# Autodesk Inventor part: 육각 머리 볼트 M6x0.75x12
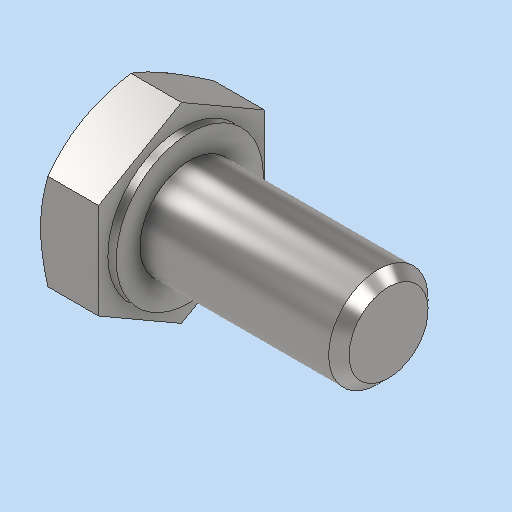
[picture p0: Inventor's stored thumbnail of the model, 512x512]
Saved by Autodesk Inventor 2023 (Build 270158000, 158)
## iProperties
Created: 2024-09
Part Number: 육각 머리 볼트 M6x0.75x12
Material: 강철, 연강
Description: 6각 머리 볼트 및 6각 머리 나사
Document SubType Name: Modeling
Designer: asung
Density: 7.85 g/cm^3
Appearance: 기본값
Author: jhkim
Sending System: Autodesk Inventor 2025
Preprocessor: ST-DEVELOPER v20
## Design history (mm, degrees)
feature "Solid1"
node "솔리드1"
